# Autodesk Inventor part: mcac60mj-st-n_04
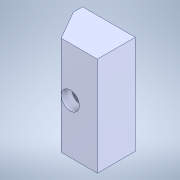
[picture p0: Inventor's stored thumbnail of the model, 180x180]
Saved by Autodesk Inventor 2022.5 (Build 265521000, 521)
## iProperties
Created: 2023-04
Part Number: mcac60mj-st-n_04
Material: Generic
Document SubType Name: Modeling
Designer: ImaoCorp
Density: 1 g/cm^3
Appearance: Default
Author: ImaoCorp
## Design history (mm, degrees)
feature "mcac60mj-st-n_04"
node "ソリッド1"
